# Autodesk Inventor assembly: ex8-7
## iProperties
Author: Administrator
Created: 2001-10
Part Number: ex8-7
Document SubType Name: Assembly
Designer: Administrator
Control State: 0
Master: False
Checked Out: False
PropertySet Name: Design Tracking Control
Shininess: 64.0
Angle Display Precision: 2
Document Length Units: 11272
Document Angle Units: 11286
Document Time Units: 11279
Document Mass Units: 11290
Document Length Units Precision: 3
Document Angle Units Precision: 2
Compacted: True
PropertySet Name: _Private Model Information
Density: 0.0
Volumn: 0.0
Area: 0.0
PropertySet Name: Model Information
